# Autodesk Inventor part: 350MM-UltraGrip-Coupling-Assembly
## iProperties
Created: 2012-05
Part Number: 350MM-UltraGrip-Coupling-Assembly
Document SubType Name: Modeling
Designer: D Cole
Density: 1 g/cm^3
Author: D Cole
